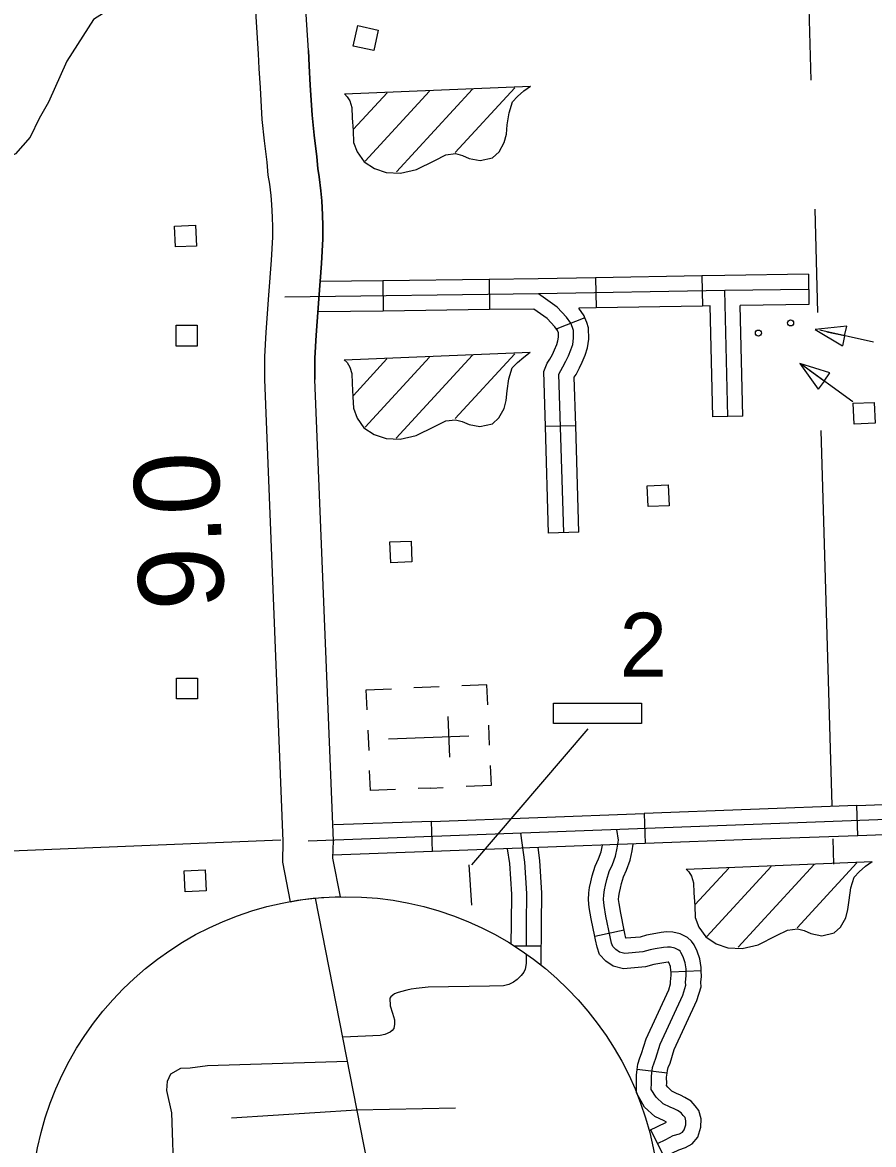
# Model space of a CAD drawing. Extents: x 1671357 to 13005564, y 567358 to 14261451.
# Drawn here: x 12758330.71 to 12758338.71, y 14259895.34 to 14259905.88 of the extents above; entities that cross this region are included whole.
import ezdxf

# ---------------------------------------------------------------- set-up
doc = ezdxf.new("R2010")
doc.units = 0
for name, color, linetype in [('10', 7, 'Continuous'), ('31', 7, 'Continuous'), ('32', 7, 'Continuous'), ('35', 7, 'Continuous'), ('48', 7, 'Continuous'), ('5', 7, 'Continuous'), ('56', 7, 'Continuous'), ('63', 7, 'Continuous')]:
    doc.layers.add(name, color=color, linetype=linetype)

msp = doc.modelspace()

# ---------------------------------------------------------------- linework, layer by layer
at = {"layer": '10'}
for points in [[(12758333.4, 14259905.617), (12758333.344, 14259906.488), (12758333.341, 14259906.54), (12758332.869, 14259906.509)], [(12758332.869, 14259906.509), (12758332.87, 14259906.484), (12758332.928, 14259905.587)], [(12758332.928, 14259905.587), (12758332.934, 14259905.447), (12758332.945, 14259905.265), (12758332.963, 14259904.969), (12758332.984, 14259904.769), (12758333.008, 14259904.567), (12758333.019, 14259904.447), (12758333.033, 14259904.362), (12758333.046, 14259904.255), (12758333.052, 14259904.17), (12758333.06, 14259904.052), (12758333.063, 14259903.956)], [(12758332.928, 14259905.587), (12758332.934, 14259905.447), (12758332.945, 14259905.265), (12758332.963, 14259904.969), (12758332.984, 14259904.769), (12758333.008, 14259904.567), (12758333.019, 14259904.447), (12758333.033, 14259904.362), (12758333.046, 14259904.255), (12758333.052, 14259904.17), (12758333.06, 14259904.052), (12758333.063, 14259903.956)], [(12758333.4, 14259905.617), (12758333.407, 14259905.473), (12758333.418, 14259905.293), (12758333.435, 14259905.008), (12758333.454, 14259904.821), (12758333.479, 14259904.618), (12758333.489, 14259904.508), (12758333.502, 14259904.429), (12758333.517, 14259904.3), (12758333.525, 14259904.204), (12758333.533, 14259904.074), (12758333.536, 14259903.969)], [(12758333.536, 14259903.969), (12758333.533, 14259904.074), (12758333.525, 14259904.204), (12758333.517, 14259904.3), (12758333.502, 14259904.429), (12758333.489, 14259904.508), (12758333.479, 14259904.618), (12758333.454, 14259904.821), (12758333.435, 14259905.008), (12758333.418, 14259905.293), (12758333.407, 14259905.473), (12758333.4, 14259905.617)], [(12758333.063, 14259903.956), (12758333.061, 14259903.864), (12758333.049, 14259903.646), (12758333.026, 14259903.318), (12758332.999, 14259902.971), (12758332.988, 14259902.738), (12758332.988, 14259902.525)], [(12758333.063, 14259903.956), (12758333.061, 14259903.864), (12758333.049, 14259903.646), (12758333.026, 14259903.318), (12758332.999, 14259902.971), (12758332.988, 14259902.738), (12758332.988, 14259902.525)], [(12758333.536, 14259903.969), (12758333.535, 14259903.848), (12758333.522, 14259903.616), (12758333.498, 14259903.283), (12758333.472, 14259902.942), (12758333.461, 14259902.726), (12758333.461, 14259902.525)], [(12758333.461, 14259902.525), (12758333.461, 14259902.726), (12758333.472, 14259902.942), (12758333.498, 14259903.283), (12758333.522, 14259903.616), (12758333.535, 14259903.848), (12758333.536, 14259903.969)], [(12758332.988, 14259902.525), (12758333.161, 14259898.188), (12758333.155, 14259897.991), (12758333.228, 14259897.619), (12758333.274, 14259897.628), (12758333.347, 14259897.639), (12758333.403, 14259897.646), (12758333.463, 14259897.652), (12758333.524, 14259897.657), (12758333.594, 14259897.662), (12758333.651, 14259897.665), (12758333.702, 14259897.665)], [(12758333.702, 14259897.665), (12758333.63, 14259898.029), (12758333.635, 14259898.19), (12758333.461, 14259902.525)], [(12758333.463, 14259897.652), (12758334.341, 14259893.183), (12758334.119, 14259891.914), (12758334.117, 14259891.779)]]:
    msp.add_lwpolyline(points, dxfattribs=at)
at = {"layer": '31'}
for p, q in [((12758338.566, 14259898.239), (12758338.555, 14259898.523)), ((12758338.555, 14259898.523), (12758338.555, 14259898.523)), ((12758336.557, 14259898.449), (12758336.567, 14259898.165)), ((12758334.568, 14259898.09), (12758334.558, 14259898.374))]:
    msp.add_line(p, q, dxfattribs=at)
for points in [[(12758345.776, 14259902.742), (12758345.895, 14259899.333), (12758345.871, 14259899.138), (12758345.83, 14259899.028), (12758345.772, 14259898.904), (12758345.67, 14259898.777), (12758345.566, 14259898.715), (12758345.459, 14259898.646), (12758345.291, 14259898.62), (12758343.392, 14259898.549), (12758341.516, 14259898.491), (12758333.398, 14259898.189)], [(12758338.555, 14259898.523), (12758337.556, 14259898.486)], [(12758338.555, 14259898.523), (12758339.555, 14259898.56)], [(12758334.558, 14259898.374), (12758335.557, 14259898.411)], [(12758335.557, 14259898.411), (12758336.557, 14259898.449)], [(12758337.556, 14259898.486), (12758336.557, 14259898.449)], [(12758334.558, 14259898.374), (12758333.64, 14259898.34)], [(12758337.567, 14259898.202), (12758336.567, 14259898.165)], [(12758338.566, 14259898.239), (12758337.567, 14259898.202)], [(12758339.565, 14259898.276), (12758338.566, 14259898.239)], [(12758335.568, 14259898.128), (12758334.568, 14259898.09)], [(12758336.567, 14259898.165), (12758335.568, 14259898.128)], [(12758334.568, 14259898.09), (12758333.631, 14259898.055)]]:
    msp.add_lwpolyline(points, dxfattribs=at)
at = {"layer": '32'}
for p, q in [((12758336.1, 14259903.482), (12758336.105, 14259903.198)), ((12758337.1, 14259903.5), (12758337.105, 14259903.216)), ((12758338.101, 14259903.514), (12758338.104, 14259903.23)), ((12758334.101, 14259903.453), (12758334.104, 14259903.169)), ((12758335.101, 14259903.466), (12758335.104, 14259903.182)), ((12758336, 14259903.105), (12758335.736, 14259903.001)), ((12758337.485, 14259902.182), (12758337.201, 14259902.176)), ((12758335.913, 14259902.091), (12758335.629, 14259902.083)), ((12758335.942, 14259901.091), (12758335.658, 14259901.083)), ((12758336.37, 14259897.351), (12758336.092, 14259897.293)), ((12758335.591, 14259897.201), (12758335.336, 14259897.202)), ((12758337.094, 14259896.968), (12758336.81, 14259896.957)), ((12758336.773, 14259896.008), (12758336.491, 14259896.043)), ((12758336.745, 14259895.221), (12758336.618, 14259895.475))]:
    msp.add_line(p, q, dxfattribs=at)
for points in [[(12758336.1, 14259903.482), (12758335.561, 14259903.472), (12758335.101, 14259903.466)], [(12758337.1, 14259903.5), (12758336.1, 14259903.482)], [(12758338.101, 14259903.514), (12758337.314, 14259903.504), (12758337.1, 14259903.5)], [(12758338.102, 14259903.372), (12758337.316, 14259903.362), (12758335.563, 14259903.33), (12758333.179, 14259903.299)], [(12758334.101, 14259903.453), (12758333.51, 14259903.446)], [(12758335.101, 14259903.466), (12758334.101, 14259903.453)], [(12758335.8, 14259901.087), (12758335.756, 14259902.575), (12758335.772, 14259902.611), (12758335.793, 14259902.645), (12758335.821, 14259902.699), (12758335.844, 14259902.747), (12758335.868, 14259902.803), (12758335.885, 14259902.855), (12758335.894, 14259902.915), (12758335.893, 14259902.987), (12758335.884, 14259903.013), (12758335.867, 14259903.056), (12758335.827, 14259903.111), (12758335.739, 14259903.207), (12758335.563, 14259903.33)], [(12758337.343, 14259902.179), (12758337.316, 14259903.362)], [(12758334.104, 14259903.169), (12758333.489, 14259903.161)], [(12758335.104, 14259903.182), (12758334.104, 14259903.169)], [(12758335.519, 14259903.188), (12758335.104, 14259903.182)], [(12758335.741, 14259902.987), (12758335.717, 14259903.021), (12758335.645, 14259903.099), (12758335.519, 14259903.188)], [(12758336.105, 14259903.198), (12758335.942, 14259903.195)], [(12758336, 14259903.105), (12758335.992, 14259903.125), (12758335.942, 14259903.195)], [(12758337.105, 14259903.216), (12758336.105, 14259903.198)], [(12758337.177, 14259903.217), (12758337.105, 14259903.216)], [(12758337.201, 14259902.176), (12758337.177, 14259903.217)], [(12758338.104, 14259903.23), (12758337.461, 14259903.221)], [(12758337.485, 14259902.182), (12758337.461, 14259903.221)], [(12758335.913, 14259902.091), (12758335.899, 14259902.547), (12758335.916, 14259902.573), (12758335.949, 14259902.636), (12758335.974, 14259902.689), (12758336.001, 14259902.753), (12758336.024, 14259902.823), (12758336.036, 14259902.905), (12758336.034, 14259903.011), (12758336.018, 14259903.062), (12758336, 14259903.105)], [(12758335.629, 14259902.083), (12758335.613, 14259902.601), (12758335.646, 14259902.678), (12758335.67, 14259902.716), (12758335.694, 14259902.762), (12758335.714, 14259902.806), (12758335.735, 14259902.854), (12758335.746, 14259902.888), (12758335.752, 14259902.924), (12758335.751, 14259902.963), (12758335.75, 14259902.965), (12758335.736, 14259903.001)], [(12758345.776, 14259902.742), (12758345.895, 14259899.333), (12758345.871, 14259899.138), (12758345.83, 14259899.028), (12758345.772, 14259898.904), (12758345.67, 14259898.777), (12758345.566, 14259898.715), (12758345.459, 14259898.646), (12758345.291, 14259898.62), (12758343.392, 14259898.549), (12758341.516, 14259898.491), (12758333.398, 14259898.189)], [(12758335.658, 14259901.083), (12758335.629, 14259902.083)], [(12758335.942, 14259901.091), (12758335.913, 14259902.091)], [(12758335.449, 14259897.201), (12758335.45, 14259897.415), (12758335.454, 14259897.695), (12758335.435, 14259897.992), (12758335.396, 14259898.263)], [(12758336.682, 14259895.348), (12758336.759, 14259895.386), (12758336.83, 14259895.421), (12758336.888, 14259895.439), (12758336.916, 14259895.455), (12758336.934, 14259895.477), (12758336.949, 14259895.523), (12758336.95, 14259895.561), (12758336.941, 14259895.591), (12758336.925, 14259895.611), (12758336.905, 14259895.635), (12758336.87, 14259895.657), (12758336.839, 14259895.672), (12758336.802, 14259895.688), (12758336.737, 14259895.72), (12758336.67, 14259895.782), (12758336.622, 14259895.854), (12758336.627, 14259895.917), (12758336.626, 14259895.98), (12758336.636, 14259896.062), (12758336.65, 14259896.106), (12758336.665, 14259896.148), (12758336.707, 14259896.281), (12758336.92, 14259896.741), (12758336.949, 14259896.834), (12758336.946, 14259896.864), (12758336.953, 14259896.923), (12758336.951, 14259896.988), (12758336.941, 14259897.046), (12758336.922, 14259897.1), (12758336.903, 14259897.143), (12758336.895, 14259897.154), (12758336.883, 14259897.165), (12758336.846, 14259897.183), (12758336.806, 14259897.193), (12758336.776, 14259897.193), (12758336.738, 14259897.188), (12758336.659, 14259897.176), (12758336.614, 14259897.166), (12758336.544, 14259897.147), (12758336.374, 14259897.132), (12758336.325, 14259897.146), (12758336.29, 14259897.169), (12758336.262, 14259897.198), (12758336.251, 14259897.23), (12758336.237, 14259897.29), (12758336.198, 14259897.484), (12758336.18, 14259897.583), (12758336.174, 14259897.639), (12758336.178, 14259897.685), (12758336.184, 14259897.729), (12758336.194, 14259897.775), (12758336.205, 14259897.827), (12758336.229, 14259897.902), (12758336.258, 14259897.969), (12758336.287, 14259898.048), (12758336.303, 14259898.121), (12758336.314, 14259898.196), (12758336.3, 14259898.297)], [(12758335.307, 14259897.221), (12758335.308, 14259897.417), (12758335.312, 14259897.691), (12758335.293, 14259897.978), (12758335.273, 14259898.117)], [(12758335.59, 14259897.021), (12758335.592, 14259897.414), (12758335.596, 14259897.698), (12758335.576, 14259898.007), (12758335.559, 14259898.127)], [(12758336.092, 14259897.293), (12758336.058, 14259897.458), (12758336.04, 14259897.563), (12758336.032, 14259897.638), (12758336.037, 14259897.701), (12758336.044, 14259897.753), (12758336.055, 14259897.805), (12758336.068, 14259897.863), (12758336.095, 14259897.952), (12758336.126, 14259898.022), (12758336.151, 14259898.088), (12758336.164, 14259898.15)], [(12758336.37, 14259897.351), (12758336.337, 14259897.511), (12758336.321, 14259897.602), (12758336.317, 14259897.641), (12758336.32, 14259897.67), (12758336.324, 14259897.705), (12758336.333, 14259897.745), (12758336.343, 14259897.79), (12758336.362, 14259897.852), (12758336.39, 14259897.916), (12758336.424, 14259898.008), (12758336.443, 14259898.096), (12758336.452, 14259898.16)], [(12758336.81, 14259896.957), (12758336.809, 14259896.973), (12758336.803, 14259897.01), (12758336.789, 14259897.048), (12758336.788, 14259897.051), (12758336.787, 14259897.051), (12758336.784, 14259897.051), (12758336.759, 14259897.048), (12758336.685, 14259897.036), (12758336.648, 14259897.028), (12758336.57, 14259897.006), (12758336.362, 14259896.989), (12758336.265, 14259897.014), (12758336.197, 14259897.06), (12758336.137, 14259897.123), (12758336.114, 14259897.192), (12758336.099, 14259897.26), (12758336.092, 14259897.293)], [(12758337.094, 14259896.968), (12758337.092, 14259897.002), (12758337.079, 14259897.082), (12758337.054, 14259897.153), (12758337.027, 14259897.214), (12758337.002, 14259897.249), (12758336.964, 14259897.284), (12758336.894, 14259897.317), (12758336.825, 14259897.334), (12758336.768, 14259897.336), (12758336.717, 14259897.329), (12758336.633, 14259897.315), (12758336.58, 14259897.304), (12758336.519, 14259897.287), (12758336.387, 14259897.276), (12758336.386, 14259897.276), (12758336.376, 14259897.32), (12758336.37, 14259897.351)], [(12758335.448, 14259897.127), (12758335.447, 14259897.039), (12758335.438, 14259896.986), (12758335.424, 14259896.957), (12758335.4, 14259896.927), (12758335.364, 14259896.888), (12758335.327, 14259896.864), (12758335.284, 14259896.841), (12758335.234, 14259896.828), (12758335.103, 14259896.825), (12758334.527, 14259896.815), (12758334.412, 14259896.805), (12758334.365, 14259896.796), (12758334.327, 14259896.789), (12758334.267, 14259896.773), (12758334.233, 14259896.764), (12758334.209, 14259896.754), (12758334.195, 14259896.742), (12758334.174, 14259896.726), (12758334.165, 14259896.712), (12758334.168, 14259896.642), (12758334.192, 14259896.573), (12758334.209, 14259896.509), (12758334.211, 14259896.469), (12758334.203, 14259896.427), (12758334.189, 14259896.409), (12758334.168, 14259896.393), (12758334.12, 14259896.37), (12758334.075, 14259896.361), (12758333.727, 14259896.345)], [(12758336.491, 14259896.043), (12758336.497, 14259896.091), (12758336.515, 14259896.151), (12758336.531, 14259896.194), (12758336.575, 14259896.332), (12758336.788, 14259896.792), (12758336.805, 14259896.848), (12758336.803, 14259896.865), (12758336.811, 14259896.929), (12758336.81, 14259896.957)], [(12758336.773, 14259896.008), (12758336.776, 14259896.032), (12758336.784, 14259896.061), (12758336.8, 14259896.102), (12758336.84, 14259896.229), (12758337.053, 14259896.69), (12758337.093, 14259896.819), (12758337.089, 14259896.863), (12758337.096, 14259896.917), (12758337.094, 14259896.968)], [(12758332.137, 14259894.985), (12758332.116, 14259895.634), (12758332.069, 14259895.846), (12758332.075, 14259895.932), (12758332.108, 14259896.002), (12758332.202, 14259896.055), (12758332.288, 14259896.057), (12758332.452, 14259896.079), (12758333.768, 14259896.122)], [(12758336.604, 14259895.468), (12758336.767, 14259895.549), (12758336.744, 14259895.559), (12758336.656, 14259895.601), (12758336.561, 14259895.689), (12758336.485, 14259895.822), (12758336.485, 14259895.922), (12758336.484, 14259895.988), (12758336.491, 14259896.043)], [(12758336.665, 14259895.181), (12758336.822, 14259895.259), (12758336.882, 14259895.289), (12758336.945, 14259895.308), (12758337.009, 14259895.345), (12758337.06, 14259895.406), (12758337.091, 14259895.499), (12758337.092, 14259895.58), (12758337.07, 14259895.657), (12758337.035, 14259895.701), (12758336.999, 14259895.744), (12758336.94, 14259895.78), (12758336.9, 14259895.801), (12758336.861, 14259895.817), (12758336.818, 14259895.838), (12758336.779, 14259895.875), (12758336.767, 14259895.892), (12758336.769, 14259895.912), (12758336.768, 14259895.971), (12758336.773, 14259896.008)], [(12758332.677, 14259895.589), (12758333.851, 14259895.664), (12758334.783, 14259895.682)]]:
    msp.add_lwpolyline(points, dxfattribs=at)
at = {"layer": '35'}
msp.add_lwpolyline([(12758332.837, 14259906.846), (12758332.641, 14259906.681), (12758332.456, 14259906.607), (12758332.421, 14259906.581), (12758332.373, 14259906.52), (12758332.313, 14259906.359), (12758332.254, 14259906.139), (12758332.232, 14259906.088), (12758332.171, 14259906.01), (12758332.124, 14259905.993), (12758331.873, 14259906.007), (12758331.682, 14259906.073), (12758331.507, 14259906.003), (12758331.474, 14259905.969), (12758331.378, 14259905.91), (12758331.128, 14259905.518), (12758330.956, 14259905.131), (12758330.87, 14259904.977), (12758330.784, 14259904.803), (12758330.647, 14259904.645), (12758330.585, 14259904.618)], dxfattribs=at)
at = {"layer": '5'}
for points in [[(12758338.024, 14259908.97), (12758338.038, 14259908.385), (12758338.125, 14259905.338)], [(12758338.16, 14259904.127), (12758338.188, 14259903.154)], [(12758338.219, 14259902.048), (12758338.32, 14259898.522)], [(12758338.33, 14259898.209), (12758338.337, 14259897.972)], [(12758333.141, 14259898.196), (12758328.142, 14259897.995)]]:
    msp.add_lwpolyline(points, dxfattribs=at)
at = {"layer": '56'}
for p, q in [((12758333.739, 14259905.21), (12758335.488, 14259905.283)), ((12758334.781, 14259904.658), (12758335.342, 14259905.267)), ((12758333.825, 14259904.877), (12758334.14, 14259905.22)), ((12758333.935, 14259904.577), (12758334.54, 14259905.234)), ((12758334.228, 14259904.476), (12758334.944, 14259905.254)), ((12758338.462, 14259903.027), (12758338.164, 14259902.997)), ((12758338.164, 14259902.997), (12758338.421, 14259902.842)), ((12758338.713, 14259902.877), (12758338.208, 14259902.989)), ((12758338.441, 14259902.935), (12758338.274, 14259902.972)), ((12758338.441, 14259902.935), (12758338.462, 14259903.027)), ((12758338.441, 14259902.935), (12758338.421, 14259902.842)), ((12758333.737, 14259902.71), (12758335.486, 14259902.783)), ((12758333.933, 14259902.078), (12758334.538, 14259902.735)), ((12758334.226, 14259901.976), (12758334.942, 14259902.755)), ((12758334.78, 14259902.158), (12758335.34, 14259902.768)), ((12758333.823, 14259902.377), (12758334.138, 14259902.72)), ((12758338.304, 14259902.587), (12758338.019, 14259902.677)), ((12758338.019, 14259902.677), (12758338.193, 14259902.434)), ((12758338.52, 14259902.315), (12758338.028, 14259902.672)), ((12758338.249, 14259902.51), (12758338.11, 14259902.611)), ((12758338.249, 14259902.51), (12758338.304, 14259902.587)), ((12758338.249, 14259902.51), (12758338.193, 14259902.434)), ((12758334.628, 14259899.639), (12758334.391, 14259899.629)), ((12758334.712, 14259899.358), (12758334.728, 14259898.977)), ((12758335.103, 14259899.089), (12758335.095, 14259899.278)), ((12758333.959, 14259899.23), (12758333.967, 14259899.041)), ((12758334.909, 14259899.176), (12758334.152, 14259899.145)), ((12758334.531, 14259899.161), (12758334.531, 14259899.161)), ((12758334.531, 14259899.161), (12758334.531, 14259899.161)), ((12758334.551, 14259898.687), (12758334.431, 14259898.682)), ((12758334.551, 14259898.687), (12758334.667, 14259898.692)), ((12758336.951, 14259897.925), (12758338.7, 14259897.998)), ((12758337.037, 14259897.593), (12758337.353, 14259897.935)), ((12758337.147, 14259897.293), (12758337.752, 14259897.95)), ((12758337.44, 14259897.191), (12758338.156, 14259897.97)), ((12758337.994, 14259897.373), (12758338.555, 14259897.983))]:
    msp.add_line(p, q, dxfattribs=at)
for points in [[(12758333.821, 14259905.659), (12758333.864, 14259905.851), (12758334.057, 14259905.808), (12758334.014, 14259905.616)], [(12758332.15, 14259903.771), (12758332.141, 14259903.968), (12758332.339, 14259903.977), (12758332.347, 14259903.78)], [(12758332.157, 14259902.839), (12758332.157, 14259903.036), (12758332.355, 14259903.036), (12758332.355, 14259902.839)], [(12758338.53, 14259902.105), (12758338.522, 14259902.302), (12758338.72, 14259902.311), (12758338.728, 14259902.114)], [(12758336.594, 14259901.331), (12758336.586, 14259901.528), (12758336.783, 14259901.536), (12758336.791, 14259901.339)], [(12758334.176, 14259900.802), (12758334.167, 14259900.999), (12758334.365, 14259901.008), (12758334.373, 14259900.811)], [(12758332.159, 14259899.524), (12758332.159, 14259899.721), (12758332.357, 14259899.721), (12758332.357, 14259899.524)], [(12758335.705, 14259899.295), (12758335.705, 14259899.484), (12758336.533, 14259899.484), (12758336.533, 14259899.295)], [(12758332.241, 14259897.712), (12758332.232, 14259897.909), (12758332.43, 14259897.918), (12758332.438, 14259897.721)]]:
    msp.add_lwpolyline(points, close=True, dxfattribs=at)
for points in [[(12758333.739, 14259905.21), (12758333.765, 14259905.183), (12758333.79, 14259905.143), (12758333.808, 14259905.081), (12758333.812, 14259904.986), (12758333.82, 14259904.864), (12758333.825, 14259904.754), (12758333.86, 14259904.664), (12758333.924, 14259904.572), (12758334.021, 14259904.508), (12758334.132, 14259904.471), (12758334.266, 14259904.464), (12758334.416, 14259904.499), (12758334.588, 14259904.584), (12758334.693, 14259904.636), (12758334.784, 14259904.648), (12758334.848, 14259904.632), (12758334.912, 14259904.603), (12758335.015, 14259904.584), (12758335.131, 14259904.61), (12758335.192, 14259904.665), (12758335.241, 14259904.753), (12758335.261, 14259904.83), (12758335.27, 14259904.919), (12758335.287, 14259905.032), (12758335.319, 14259905.136), (12758335.367, 14259905.185), (12758335.427, 14259905.237), (12758335.488, 14259905.283)], [(12758333.737, 14259902.71), (12758333.763, 14259902.684), (12758333.788, 14259902.643), (12758333.807, 14259902.581), (12758333.81, 14259902.487), (12758333.818, 14259902.364), (12758333.823, 14259902.255), (12758333.858, 14259902.164), (12758333.922, 14259902.073), (12758334.019, 14259902.009), (12758334.13, 14259901.972), (12758334.264, 14259901.964), (12758334.414, 14259901.999), (12758334.586, 14259902.085), (12758334.691, 14259902.136), (12758334.782, 14259902.148), (12758334.846, 14259902.132), (12758334.91, 14259902.104), (12758335.013, 14259902.084), (12758335.13, 14259902.11), (12758335.19, 14259902.165), (12758335.239, 14259902.253), (12758335.259, 14259902.33), (12758335.268, 14259902.42), (12758335.285, 14259902.533), (12758335.317, 14259902.636), (12758335.365, 14259902.685), (12758335.425, 14259902.737), (12758335.486, 14259902.783)], [(12758333.951, 14259899.421), (12758333.943, 14259899.61), (12758334.18, 14259899.62)], [(12758335.087, 14259899.468), (12758335.079, 14259899.657), (12758334.842, 14259899.647)], [(12758336.027, 14259899.242), (12758334.934, 14259897.964)], [(12758334.219, 14259898.674), (12758333.983, 14259898.664), (12758333.975, 14259898.853)], [(12758335.11, 14259898.9), (12758335.118, 14259898.711), (12758334.882, 14259898.701)], [(12758336.951, 14259897.925), (12758336.977, 14259897.899), (12758337.002, 14259897.858), (12758337.021, 14259897.796), (12758337.025, 14259897.702), (12758337.032, 14259897.579), (12758337.037, 14259897.47), (12758337.072, 14259897.38), (12758337.136, 14259897.288), (12758337.233, 14259897.224), (12758337.344, 14259897.187), (12758337.478, 14259897.179), (12758337.629, 14259897.214), (12758337.8, 14259897.3), (12758337.906, 14259897.351), (12758337.997, 14259897.363), (12758338.06, 14259897.347), (12758338.124, 14259897.319), (12758338.227, 14259897.299), (12758338.344, 14259897.325), (12758338.404, 14259897.38), (12758338.453, 14259897.469), (12758338.473, 14259897.545), (12758338.483, 14259897.635), (12758338.499, 14259897.748), (12758338.531, 14259897.851), (12758338.579, 14259897.9), (12758338.639, 14259897.953), (12758338.7, 14259897.998)], [(12758334.907, 14259897.964), (12758334.934, 14259897.588)]]:
    msp.add_lwpolyline(points, dxfattribs=at)
for centre in [(12758337.934, 14259903.057), (12758337.631, 14259902.962)]:
    msp.add_circle(centre, 0.0284, dxfattribs=at)
at = {"layer": '63'}
msp.add_circle((12758333.748, 14259894.711), 2.955, dxfattribs=at)

# ---------------------------------------------------------------- texts
at = {"layer": '48'}
msp.add_text('9.0', height=0.8001, rotation=92.4506, dxfattribs=at).set_placement((12758332.612, 14259900.376))
at = {"layer": '56'}
msp.add_text('2', height=0.6, dxfattribs=at).set_placement((12758336.326, 14259899.734))

doc.saveas('drawing.dxf')
